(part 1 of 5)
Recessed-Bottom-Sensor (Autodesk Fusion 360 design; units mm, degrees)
parameter "FrameLength" = 640 comment "Fixed existing outer length"
parameter "FrameWidth" = 190 comment "Fixed existing outer width"
parameter "FrameHeight" = 110 comment "Fixed existing height"
parameter "PivotHeight" = 18 comment "Above frame center"
parameter "LeverTravel" = 100 comment "Stable endpoint to endpoint"
parameter "PrintClearance" = 0.3 comment "Prototype diametral running clearance"
base_mesh_feature "Base Mesh Feature"
ground "Pin1"
work_plane "WorkPlane1" AlongDistance -36 ExtraOffset 0
sketch "Flat load-bearing plate" plane through (-36, 0, 0) normal (1, 0, 0) x axis (0, 0, -1)
  line L1 (-33, -55) -> (-33, -75)
  line L2 (2, -55) -> (-33, -55)
  line L3 (2, 55) -> (2, -55)
  line L4 (-33, 55) -> (2, 55)
  line L5 (-33, 75) -> (-33, 55)
  line L6 (-57, 75) -> (-33, 75)
  line L7 (-57, 32) -> (-57, 75)
  line L8 (-86, 26) -> (-57, 32)
  line L9 (-86, -26) -> (-86, 26)
  line L10 (-57, -32) -> (-86, -26)
  line L11 (-57, -75) -> (-57, -32)
  line L12 (-33, -75) -> (-57, -75)
extrude "Extrude1" new body sketch "Flat load-bearing plate" along normal blind 12
work_plane "WorkPlane2" AlongDistance -37 ExtraOffset 0
sketch "Replaceable bushing seat" plane through (-37, 0, 0) normal (1, 0, 0) x axis (0, 0, -1)
  circle C1 centre (-65, 0) radius 10.15
extrude "Extrude2" cut sketch "Replaceable bushing seat" along normal blind 14
work_plane "WorkPlane3" AlongDistance -37 ExtraOffset 0
sketch "Follower pivot bolt" plane through (-37, 0, 0) normal (1, 0, 0) x axis (0, 0, -1)
  circle C1 centre (-12, -35) radius 2.7
extrude "Extrude3" cut sketch "Follower pivot bolt" along normal blind 14
work_plane "WorkPlane4" AlongDistance -76 ExtraOffset 0
sketch "M5 rail mounting bore" plane through (0, -76, 0) normal (0, 1, 0) x axis (1, 0, 0)
  circle C1 centre (-30, -45) radius 2.7
extrude "Extrude4" cut sketch "M5 rail mounting bore" along normal blind 22
work_plane "WorkPlane5" AlongDistance -55 ExtraOffset 0
sketch "Rail screw tool and washer access" plane through (0, -55, 0) normal (0, 1, 0) x axis (1, 0, 0)
  circle C1 centre (-30, -45) radius 5.3
extrude "Extrude5" cut sketch "Rail screw tool and washer access" along normal blind 12
work_plane "WorkPlane6" AlongDistance 54 ExtraOffset 0
sketch "M5 rail mounting bore (1)" plane through (0, 54, 0) normal (0, 1, 0) x axis (1, 0, 0)
  circle C1 centre (-30, -45) radius 2.7
extrude "Extrude6" cut sketch "M5 rail mounting bore (1)" along normal blind 22
work_plane "WorkPlane7" AlongDistance 43 ExtraOffset 0
sketch "Rail screw tool and washer access (1)" plane through (0, 43, 0) normal (0, 1, 0) x axis (1, 0, 0)
  circle C1 centre (-30, -45) radius 5.3
extrude "Extrude7" cut sketch "Rail screw tool and washer access (1)" along normal blind 12
work_plane "WorkPlane8" AlongDistance -37 ExtraOffset 0
sketch "Spring crossblock attachment" plane through (-37, 0, 0) normal (1, 0, 0) x axis (0, 0, -1)
  circle C1 centre (-44, -59) radius 1.7
extrude "Extrude8" cut sketch "Spring crossblock attachment" along normal blind 14
work_plane "WorkPlane9" AlongDistance -37 ExtraOffset 0
sketch "Spring crossblock attachment (1)" plane through (-37, 0, 0) normal (1, 0, 0) x axis (0, 0, -1)
  circle C1 centre (-44, -51) radius 1.7
extrude "Extrude9" cut sketch "Spring crossblock attachment (1)" along normal blind 14
work_plane "WorkPlane1" AlongDistance 24 ExtraOffset 0
sketch "Flat load-bearing plate" plane through (24, 0, 0) normal (1, 0, 0) x axis (0, 0, -1)
  line L1 (-33, -55) -> (-33, -75)
  line L2 (2, -55) -> (-33, -55)
  line L3 (2, 55) -> (2, -55)
  line L4 (-33, 55) -> (2, 55)
  line L5 (-33, 75) -> (-33, 55)
  line L6 (-57, 75) -> (-33, 75)
  line L7 (-57, 32) -> (-57, 75)
  line L8 (-86, 26) -> (-57, 32)
  line L9 (-86, -26) -> (-86, 26)
  line L10 (-57, -32) -> (-86, -26)
  line L11 (-57, -75) -> (-57, -32)
  line L12 (-33, -75) -> (-57, -75)
extrude "Extrude1" new body sketch "Flat load-bearing plate" along normal blind 12
work_plane "WorkPlane2" AlongDistance 23 ExtraOffset 0
sketch "Replaceable bushing seat" plane through (23, 0, 0) normal (1, 0, 0) x axis (0, 0, -1)
  circle C1 centre (-65, 0) radius 10.15
extrude "Extrude2" cut sketch "Replaceable bushing seat" along normal blind 14
work_plane "WorkPlane3" AlongDistance 23 ExtraOffset 0
sketch "Follower pivot bolt" plane through (23, 0, 0) normal (1, 0, 0) x axis (0, 0, -1)
  circle C1 centre (-12, -35) radius 2.7
extrude "Extrude3" cut sketch "Follower pivot bolt" along normal blind 14
work_plane "WorkPlane4" AlongDistance -76 ExtraOffset 0
sketch "M5 rail mounting bore" plane through (0, -76, 0) normal (0, 1, 0) x axis (1, 0, 0)
  circle C1 centre (30, -45) radius 2.7
extrude "Extrude4" cut sketch "M5 rail mounting bore" along normal blind 22
work_plane "WorkPlane5" AlongDistance -55 ExtraOffset 0
sketch "Rail screw tool and washer access" plane through (0, -55, 0) normal (0, 1, 0) x axis (1, 0, 0)
  circle C1 centre (30, -45) radius 5.3
extrude "Extrude5" cut sketch "Rail screw tool and washer access" along normal blind 12
work_plane "WorkPlane6" AlongDistance 54 ExtraOffset 0
sketch "M5 rail mounting bore (1)" plane through (0, 54, 0) normal (0, 1, 0) x axis (1, 0, 0)
  circle C1 centre (30, -45) radius 2.7
extrude "Extrude6" cut sketch "M5 rail mounting bore (1)" along normal blind 22
work_plane "WorkPlane7" AlongDistance 43 ExtraOffset 0
sketch "Rail screw tool and washer access (1)" plane through (0, 43, 0) normal (0, 1, 0) x axis (1, 0, 0)
  circle C1 centre (30, -45) radius 5.3
extrude "Extrude7" cut sketch "Rail screw tool and washer access (1)" along normal blind 12
work_plane "WorkPlane8" AlongDistance 23 ExtraOffset 0
sketch "Spring crossblock attachment" plane through (23, 0, 0) normal (1, 0, 0) x axis (0, 0, -1)
  circle C1 centre (-44, -59) radius 1.7
extrude "Extrude8" cut sketch "Spring crossblock attachment" along normal blind 14
work_plane "WorkPlane9" AlongDistance 23 ExtraOffset 0
sketch "Spring crossblock attachment (1)" plane through (23, 0, 0) normal (1, 0, 0) x axis (0, 0, -1)
  circle C1 centre (-44, -51) radius 1.7
extrude "Extrude9" cut sketch "Spring crossblock attachment (1)" along normal blind 14
work_plane "WorkPlane1" AlongDistance -36 ExtraOffset 0
sketch "Replaceable journal body" plane through (-36, 0, 0) normal (1, 0, 0) x axis (0, 0, -1)
  circle C1 centre (-65, 0) radius 10.05
extrude "Extrude1" new body sketch "Replaceable journal body" along normal blind 12 bodies "P03 Left flanged journal bush"
work_plane "WorkPlane2" AlongDistance -37.2 ExtraOffset 0
sketch "Axial thrust flange" plane through (-37.2, 0, 0) normal (1, 0, 0) x axis (0, 0, -1)
  circle C1 centre (-65, 0) radius 12.75
extrude "Extrude2" add sketch "Axial thrust flange" along normal blind 1.2
work_plane "WorkPlane3" AlongDistance -38 ExtraOffset 0
sketch "Running journal bore" plane through (-38, 0, 0) normal (1, 0, 0) x axis (0, 0, -1)
  circle C1 centre (-65, 0) radius 6.15
extrude "Extrude3" cut sketch "Running journal bore" along normal blind 15
work_plane "WorkPlane1" AlongDistance 24 ExtraOffset 0
sketch "Replaceable journal body" plane through (24, 0, 0) normal (1, 0, 0) x axis (0, 0, -1)
  circle C1 centre (-65, 0) radius 10.05
extrude "Extrude1" new body sketch "Replaceable journal body" along normal blind 12 bodies "P04 Right flanged journal bush"
work_plane "WorkPlane2" AlongDistance 36 ExtraOffset 0
sketch "Axial thrust flange" plane through (36, 0, 0) normal (1, 0, 0) x axis (0, 0, -1)
  circle C1 centre (-65, 0) radius 12.75
extrude "Extrude2" add sketch "Axial thrust flange" along normal blind 1.2
work_plane "WorkPlane3" AlongDistance 23 ExtraOffset 0
sketch "Running journal bore" plane through (23, 0, 0) normal (1, 0, 0) x axis (0, 0, -1)
  circle C1 centre (-65, 0) radius 6.15
extrude "Extrude3" cut sketch "Running journal bore" along normal blind 15
work_plane "WorkPlane1" AlongDistance -39.35 ExtraOffset 0
sketch "Axial cap" plane through (-39.35, 0, 0) normal (1, 0, 0) x axis (0, 0, -1)
  circle C1 centre (-65, 0) radius 10
extrude "Extrude1" new body sketch "Axial cap" along normal blind 2 bodies "P06 Shaft retaining cap"
work_plane "WorkPlane2" AlongDistance -39.5 ExtraOffset 0
sketch "M3 cap screw" plane through (-39.5, 0, 0) normal (1, 0, 0) x axis (0, 0, -1)
  circle C1 centre (-65, 0) radius 1.7
extrude "Extrude2" cut sketch "M3 cap screw" along normal blind 2.4
work_plane "WorkPlane1" AlongDistance -7 ExtraOffset 0
sketch "Main lever hub" plane through (-7, 0, 0) normal (1, 0, 0) x axis (0, 0, -1)
  circle C1 centre (-65, 0) radius 22
extrude "Extrude1" new body sketch "Main lever hub" along normal blind 14 bodies "P07 Integral lever rotor and cam carrier"
work_plane "WorkPlane2" AlongDistance -7 ExtraOffset 0
sketch "Continuous reinforced lever stem" plane through (-7, 0, 0) normal (1, 0, 0) x axis (0, 0, -1)
  line L1 (-60, 14) -> (-60, -14)
  line L2 (-95, 11) -> (-60, 14)
  line L3 (-150, 7) -> (-95, 11)
  line L4 (-195, 7) -> (-150, 7)
  line L5 (-195, -7) -> (-195, 7)
  line L6 (-150, -7) -> (-195, -7)
  line L7 (-95, -11) -> (-150, -7)
  line L8 (-60, -14) -> (-95, -11)
extrude "Extrude2" add sketch "Continuous reinforced lever stem" along normal blind 14
work_plane "WorkPlane3" AlongDistance -7 ExtraOffset 0
sketch "Integrated cam carrier fan" plane through (-7, 0, 0) normal (1, 0, 0) x axis (0, 0, -1)
  line L1 (-44.5, 35.507) -> (-65, 0)
  line L2 (-42.6698, 34.3855) -> (-44.5, 35.507)
  line L3 (-40.9008, 33.1697) -> (-42.6698, 34.3855)
  line L4 (-39.1979, 31.863) -> (-40.9008, 33.1697)
  line L5 (-37.5656, 30.4689) -> (-39.1979, 31.863)
  line L6 (-36.0086, 28.9914) -> (-37.5656, 30.4689)
  line L7 (-34.5311, 27.4344) -> (-36.0086, 28.9914)
  line L8 (-33.137, 25.8021) -> (-34.5311, 27.4344)
  line L9 (-31.8303, 24.0992) -> (-33.137, 25.8021)
  line L10 (-30.6145, 22.3302) -> (-31.8303, 24.0992)
  line L11 (-29.493, 20.5) -> (-30.6145, 22.3302)
  line L12 (-28.4687, 18.6136) -> (-29.493, 20.5)
  line L13 (-27.5446, 16.6762) -> (-28.4687, 18.6136)
  line L14 (-26.7232, 14.6931) -> (-27.5446, 16.6762)
  line L15 (-26.0067, 12.6697) -> (-26.7232, 14.6931)
  line L16 (-25.397, 10.6116) -> (-26.0067, 12.6697)
  line L17 (-24.8959, 8.5244) -> (-25.397, 10.6116)
  line L18 (-24.5048, 6.4138) -> (-24.8959, 8.5244)
  line L19 (-24.2246, 4.2857) -> (-24.5048, 6.4138)
  line L20 (-24.0562, 2.1458) -> (-24.2246, 4.2857)
  line L21 (-24, 0) -> (-24.0562, 2.1458)
  line L22 (-24.0562, -2.1458) -> (-24, 0)
  line L23 (-24.2246, -4.2857) -> (-24.0562, -2.1458)
  line L24 (-24.5048, -6.4138) -> (-24.2246, -4.2857)
  line L25 (-24.8959, -8.5244) -> (-24.5048, -6.4138)
  line L26 (-25.397, -10.6116) -> (-24.8959, -8.5244)
  line L27 (-26.0067, -12.6697) -> (-25.397, -10.6116)
  line L28 (-26.7232, -14.6931) -> (-26.0067, -12.6697)
  line L29 (-27.5446, -16.6762) -> (-26.7232, -14.6931)
  line L30 (-28.4687, -18.6136) -> (-27.5446, -16.6762)
  line L31 (-29.493, -20.5) -> (-28.4687, -18.6136)
  line L32 (-30.6145, -22.3302) -> (-29.493, -20.5)
  line L33 (-31.8303, -24.0992) -> (-30.6145, -22.3302)
  line L34 (-33.137, -25.8021) -> (-31.8303, -24.0992)
  line L35 (-34.5311, -27.4344) -> (-33.137, -25.8021)
  line L36 (-36.0086, -28.9914) -> (-34.5311, -27.4344)
  line L37 (-37.5656, -30.4689) -> (-36.0086, -28.9914)
  line L38 (-39.1979, -31.863) -> (-37.5656, -30.4689)
  line L39 (-40.9008, -33.1697) -> (-39.1979, -31.863)
  line L40 (-42.6698, -34.3855) -> (-40.9008, -33.1697)
  line L41 (-44.5, -35.507) -> (-42.6698, -34.3855)
  line L42 (-65, 0) -> (-44.5, -35.507)
extrude "Extrude3" add sketch "Integrated cam carrier fan" along normal blind 14
work_plane "WorkPlane4" AlongDistance -23.6 ExtraOffset 0
sketch "Integral axial locating hub" plane through (-23.6, 0, 0) normal (1, 0, 0) x axis (0, 0, -1)
  circle C1 centre (-65, 0) radius 10
work_plane "WorkPlane5" AlongDistance -24 ExtraOffset 0
sketch "D shaft socket" plane through (-24, 0, 0) normal (1, 0, 0) x axis (0, 0, -1)
  line L1 (-69.6247, 6.65) -> (-60.3753, 6.65)
  arc A1 centre (-65, 0) radius 8.1 clockwise from (-60.3753, 6.65) to (-69.6247, 6.65)
extrude "Extrude5" cut sketch "D shaft socket" along normal blind 48
work_plane "WorkPlane6" AlongDistance 0.3 ExtraOffset 0
sketch "Cam M3 insert pocket" plane through (0.3, 0, 0) normal (1, 0, 0) x axis (0, 0, -1)
  circle C1 centre (-39.5442, 25.4558) radius 2
extrude "Extrude6" cut sketch "Cam M3 insert pocket" along normal blind 6.8
work_plane "WorkPlane7" AlongDistance 0.3 ExtraOffset 0
sketch "Cam M3 insert pocket (1)" plane through (0.3, 0, 0) normal (1, 0, 0) x axis (0, 0, -1)
  circle C1 centre (-29, 0) radius 2
extrude "Extrude7" cut sketch "Cam M3 insert pocket (1)" along normal blind 6.8
work_plane "WorkPlane8" AlongDistance 0.3 ExtraOffset 0
sketch "Cam M3 insert pocket (2)" plane through (0.3, 0, 0) normal (1, 0, 0) x axis (0, 0, -1)
  circle C1 centre (-39.5442, -25.4558) radius 2
extrude "Extrude8" cut sketch "Cam M3 insert pocket (2)" along normal blind 6.8
work_plane "WorkPlane9" AlongDistance -8 ExtraOffset 0
sketch "Grip through bolt" plane through (-8, 0, 0) normal (1, 0, 0) x axis (0, 0, -1)
  circle C1 centre (-180, 0) radius 1.7
extrude "Extrude9" cut sketch "Grip through bolt" along normal blind 16
work_plane "WorkPlane10" AlongDistance -8 ExtraOffset 0
sketch "Grip through bolt (1)" plane through (-8, 0, 0) normal (1, 0, 0) x axis (0, 0, -1)
  circle C1 centre (-190, 0) radius 1.7
extrude "Extrude10" cut sketch "Grip through bolt (1)" along normal blind 16
work_plane "WorkPlane1" AlongDistance 7 ExtraOffset 0
sketch "Roller compensated replaceable cam" plane through (7, 0, 0) normal (1, 0, 0) x axis (0, 0, -1)
  line L1 (-39.4967, 42.2602) -> (-39.6212, 42.3096)
  line L2 (-39.3834, 42.211) -> (-39.4967, 42.2602)
  line L3 (-39.2796, 42.1617) -> (-39.3834, 42.211)
  line L4 (-39.1836, 42.1119) -> (-39.2796, 42.1617)
  line L5 (-39.0932, 42.0608) -> (-39.1836, 42.1119)
  line L6 (-39.0065, 42.0075) -> (-39.0932, 42.0608)
  line L7 (-38.9215, 41.9508) -> (-39.0065, 42.0075)
  line L8 (-38.8363, 41.8895) -> (-38.9215, 41.9508)
  line L9 (-38.7492, 41.8219) -> (-38.8363, 41.8895)
  line L10 (-38.6586, 41.7465) -> (-38.7492, 41.8219)
  line L11 (-38.5633, 41.6619) -> (-38.6586, 41.7465)
  line L12 (-38.4623, 41.5665) -> (-38.5633, 41.6619)
  line L13 (-38.3549, 41.459) -> (-38.4623, 41.5665)
  line L14 (-38.2404, 41.3384) -> (-38.3549, 41.459)
  line L15 (-38.1184, 41.204) -> (-38.2404, 41.3384)
  line L16 (-37.9886, 41.055) -> (-38.1184, 41.204)
  line L17 (-37.8508, 40.8913) -> (-37.9886, 41.055)
  line L18 (-37.7045, 40.7127) -> (-37.8508, 40.8913)
  line L19 (-37.5496, 40.5196) -> (-37.7045, 40.7127)
  line L20 (-37.3856, 40.3123) -> (-37.5496, 40.5196)
  line L21 (-37.2122, 40.0915) -> (-37.3856, 40.3123)
  line L22 (-37.0289, 39.858) -> (-37.2122, 40.0915)
  line L23 (-36.8353, 39.6128) -> (-37.0289, 39.858)
  line L24 (-36.6306, 39.3571) -> (-36.8353, 39.6128)
  line L25 (-36.4145, 39.0923) -> (-36.6306, 39.3571)
  line L26 (-36.1865, 38.82) -> (-36.4145, 39.0923)
  line L27 (-35.9461, 38.5417) -> (-36.1865, 38.82)
  line L28 (-35.6932, 38.2594) -> (-35.9461, 38.5417)
  line L29 (-35.4277, 37.9751) -> (-35.6932, 38.2594)
  line L30 (-35.15, 37.6908) -> (-35.4277, 37.9751)
  line L31 (-34.8607, 37.4087) -> (-35.15, 37.6908)
  line L32 (-34.5606, 37.1307) -> (-34.8607, 37.4087)
  line L33 (-34.2512, 36.859) -> (-34.5606, 37.1307)
  line L34 (-33.934, 36.5953) -> (-34.2512, 36.859)
  line L35 (-33.6109, 36.341) -> (-33.934, 36.5953)
  line L36 (-33.2841, 36.0975) -> (-33.6109, 36.341)
  line L37 (-32.9558, 35.8655) -> (-33.2841, 36.0975)
  line L38 (-32.6282, 35.6454) -> (-32.9558, 35.8655)
  line L39 (-32.3036, 35.4375) -> (-32.6282, 35.6454)
  line L40 (-31.984, 35.2415) -> (-32.3036, 35.4375)
  line L41 (-31.6712, 35.057) -> (-31.984, 35.2415)
  line L42 (-31.3671, 34.8833) -> (-31.6712, 35.057)
  line L43 (-31.073, 34.7197) -> (-31.3671, 34.8833)
  line L44 (-30.7902, 34.5655) -> (-31.073, 34.7197)
  line L45 (-30.52, 34.4197) -> (-30.7902, 34.5655)
  line L46 (-30.263, 34.2816) -> (-30.52, 34.4197)
  line L47 (-30.0201, 34.1506) -> (-30.263, 34.2816)
  line L48 (-29.7919, 34.0259) -> (-30.0201, 34.1506)
  line L49 (-29.5787, 33.9071) -> (-29.7919, 34.0259)
  line L50 (-29.3807, 33.7939) -> (-29.5787, 33.9071)
  line L51 (-29.1982, 33.6858) -> (-29.3807, 33.7939)
  line L52 (-29.0309, 33.5827) -> (-29.1982, 33.6858)
  line L53 (-28.8786, 33.4843) -> (-29.0309, 33.5827)
  line L54 (-28.7406, 33.3906) -> (-28.8786, 33.4843)
  line L55 (-28.6164, 33.3013) -> (-28.7406, 33.3906)
  line L56 (-28.5047, 33.2161) -> (-28.6164, 33.3013)
  line L57 (-28.4046, 33.1346) -> (-28.5047, 33.2161)
  line L58 (-28.3144, 33.0563) -> (-28.4046, 33.1346)
  line L59 (-28.2327, 32.9802) -> (-28.3144, 33.0563)
  line L60 (-28.1577, 32.9052) -> (-28.2327, 32.9802)
  line L61 (-28.0879, 32.8301) -> (-28.1577, 32.9052)
  line L62 (-28.0214, 32.7532) -> (-28.0879, 32.8301)
  line L63 (-27.9569, 32.6728) -> (-28.0214, 32.7532)
  line L64 (-27.893, 32.5869) -> (-27.9569, 32.6728)
  line L65 (-27.8285, 32.4936) -> (-27.893, 32.5869)
  line L66 (-27.7627, 32.3911) -> (-27.8285, 32.4936)
  line L67 (-27.6947, 32.2776) -> (-27.7627, 32.3911)
  line L68 (-27.6241, 32.1514) -> (-27.6947, 32.2776)
  line L69 (-27.5507, 32.0113) -> (-27.6241, 32.1514)
  line L70 (-27.4742, 31.8562) -> (-27.5507, 32.0113)
  line L71 (-27.3945, 31.6853) -> (-27.4742, 31.8562)
  line L72 (-27.3113, 31.4981) -> (-27.3945, 31.6853)
  line L73 (-27.2245, 31.2943) -> (-27.3113, 31.4981)
  line L74 (-27.1338, 31.074) -> (-27.2245, 31.2943)
  line L75 (-27.0388, 30.8373) -> (-27.1338, 31.074)
  line L76 (-26.939, 30.5847) -> (-27.0388, 30.8373)
  line L77 (-26.8337, 30.3166) -> (-26.939, 30.5847)
  line L78 (-26.7223, 30.034) -> (-26.8337, 30.3166)
  line L79 (-26.6038, 29.7375) -> (-26.7223, 30.034)
  line L80 (-26.4775, 29.4284) -> (-26.6038, 29.7375)
  line L81 (-26.3424, 29.1079) -> (-26.4775, 29.4284)
  line L82 (-26.1977, 28.7772) -> (-26.3424, 29.1079)
  line L83 (-26.0425, 28.4382) -> (-26.1977, 28.7772)
  line L84 (-25.8761, 28.0925) -> (-26.0425, 28.4382)
  line L85 (-25.6981, 27.7422) -> (-25.8761, 28.0925)
  line L86 (-25.5084, 27.3893) -> (-25.6981, 27.7422)
  line L87 (-25.3069, 27.0362) -> (-25.5084, 27.3893)
  line L88 (-25.0943, 26.6851) -> (-25.3069, 27.0362)
  line L89 (-24.8713, 26.3382) -> (-25.0943, 26.6851)
  line L90 (-24.6392, 25.9976) -> (-24.8713, 26.3382)
  line L91 (-24.3995, 25.6653) -> (-24.6392, 25.9976)
  line L92 (-24.1539, 25.3428) -> (-24.3995, 25.6653)
  line L93 (-23.9045, 25.0314) -> (-24.1539, 25.3428)
  line L94 (-23.6532, 24.7321) -> (-23.9045, 25.0314)
  line L95 (-23.4022, 24.4455) -> (-23.6532, 24.7321)
  line L96 (-23.1534, 24.1718) -> (-23.4022, 24.4455)
  line L97 (-22.9088, 23.9111) -> (-23.1534, 24.1718)
  line L98 (-22.6701, 23.6631) -> (-22.9088, 23.9111)
  line L99 (-22.4387, 23.4276) -> (-22.6701, 23.6631)
  line L100 (-22.2162, 23.204) -> (-22.4387, 23.4276)
  line L101 (-22.0036, 22.9918) -> (-22.2162, 23.204)
  line L102 (-21.8021, 22.7907) -> (-22.0036, 22.9918)
  line L103 (-21.6123, 22.6001) -> (-21.8021, 22.7907)
  line L104 (-21.435, 22.4197) -> (-21.6123, 22.6001)
  line L105 (-21.2706, 22.2491) -> (-21.435, 22.4197)
  line L106 (-21.1193, 22.088) -> (-21.2706, 22.2491)
  line L107 (-20.9813, 21.9362) -> (-21.1193, 22.088)
  line L108 (-20.8565, 21.7934) -> (-20.9813, 21.9362)
  line L109 (-20.7443, 21.6594) -> (-20.8565, 21.7934)
  line L110 (-20.6444, 21.5337) -> (-20.7443, 21.6594)
  line L111 (-20.556, 21.4159) -> (-20.6444, 21.5337)
  line L112 (-20.478, 21.3055) -> (-20.556, 21.4159)
  line L113 (-20.4094, 21.2014) -> (-20.478, 21.3055)
  line L114 (-20.349, 21.1027) -> (-20.4094, 21.2014)
  line L115 (-20.2954, 21.0079) -> (-20.349, 21.1027)
  line L116 (-20.2475, 20.9154) -> (-20.2954, 21.0079)
  line L117 (-20.2039, 20.8234) -> (-20.2475, 20.9154)
  line L118 (-20.1637, 20.7297) -> (-20.2039, 20.8234)
  line L119 (-20.126, 20.6321) -> (-20.1637, 20.7297)
  line L120 (-20.0901, 20.5286) -> (-20.126, 20.6321)
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extrude "Extrude1" new body sketch "Roller compensated replaceable cam" along normal blind 8 bodies "P08 Cam 7 gates - stable endpoints"
work_plane "WorkPlane2" AlongDistance 6.9 ExtraOffset 0
sketch "Cam screw clearance" plane through (6.9, 0, 0) normal (1, 0, 0) x axis (0, 0, -1)
  circle C1 centre (-39.5442, 25.4558) radius 1.7
extrude "Extrude2" cut sketch "Cam screw clearance" along normal blind 8.2
work_plane "WorkPlane3" AlongDistance 12 ExtraOffset 0
sketch "Cam head recess" plane through (12, 0, 0) normal (1, 0, 0) x axis (0, 0, -1)
  circle C1 centre (-39.5442, 25.4558) radius 3.1
extrude "Extrude3" cut sketch "Cam head recess" along normal blind 3.1
work_plane "WorkPlane4" AlongDistance 6.9 ExtraOffset 0
sketch "Cam screw clearance (1)" plane through (6.9, 0, 0) normal (1, 0, 0) x axis (0, 0, -1)
  circle C1 centre (-29, 0) radius 1.7
extrude "Extrude4" cut sketch "Cam screw clearance (1)" along normal blind 8.2
work_plane "WorkPlane5" AlongDistance 12 ExtraOffset 0
sketch "Cam head recess (1)" plane through (12, 0, 0) normal (1, 0, 0) x axis (0, 0, -1)
  circle C1 centre (-29, 0) radius 3.1
extrude "Extrude5" cut sketch "Cam head recess (1)" along normal blind 3.1
work_plane "WorkPlane6" AlongDistance 6.9 ExtraOffset 0
sketch "Cam screw clearance (2)" plane through (6.9, 0, 0) normal (1, 0, 0) x axis (0, 0, -1)
  circle C1 centre (-39.5442, -25.4558) radius 1.7
extrude "Extrude6" cut sketch "Cam screw clearance (2)" along normal blind 8.2
work_plane "WorkPlane7" AlongDistance 12 ExtraOffset 0
sketch "Cam head recess (2)" plane through (12, 0, 0) normal (1, 0, 0) x axis (0, 0, -1)
  circle C1 centre (-39.5442, -25.4558) radius 3.1
extrude "Extrude7" cut sketch "Cam head recess (2)" along normal blind 3.1
work_plane "WorkPlane1" AlongDistance 7 ExtraOffset 0
sketch "Roller compensated replaceable cam" plane through (7, 0, 0) normal (1, 0, 0) x axis (0, 0, -1)
  line L1 (-40.6423, 42.8316) -> (-40.8055, 42.9534)
  line L2 (-40.4783, 42.705) -> (-40.6423, 42.8316)
  line L3 (-40.3132, 42.5736) -> (-40.4783, 42.705)
  line L4 (-40.1469, 42.4372) -> (-40.3132, 42.5736)
  line L5 (-39.9791, 42.2958) -> (-40.1469, 42.4372)
  line L6 (-39.8097, 42.1493) -> (-39.9791, 42.2958)
  line L7 (-39.6386, 41.9977) -> (-39.8097, 42.1493)
  line L8 (-39.4656, 41.8411) -> (-39.6386, 41.9977)
  line L9 (-39.2906, 41.6794) -> (-39.4656, 41.8411)
  line L10 (-39.1134, 41.5128) -> (-39.2906, 41.6794)
  line L11 (-38.9338, 41.3413) -> (-39.1134, 41.5128)
  line L12 (-38.7519, 41.165) -> (-38.9338, 41.3413)
  line L13 (-38.5674, 40.9842) -> (-38.7519, 41.165)
  line L14 (-38.3803, 40.7991) -> (-38.5674, 40.9842)
  line L15 (-38.1904, 40.6097) -> (-38.3803, 40.7991)
  line L16 (-37.9976, 40.4164) -> (-38.1904, 40.6097)
  line L17 (-37.8019, 40.2195) -> (-37.9976, 40.4164)
  line L18 (-37.6031, 40.0191) -> (-37.8019, 40.2195)
  line L19 (-37.4011, 39.8157) -> (-37.6031, 40.0191)
  line L20 (-37.1958, 39.6094) -> (-37.4011, 39.8157)
  line L21 (-36.9872, 39.4008) -> (-37.1958, 39.6094)
  line L22 (-36.7753, 39.19) -> (-36.9872, 39.4008)
  line L23 (-36.5599, 38.9775) -> (-36.7753, 39.19)
  line L24 (-36.3411, 38.7636) -> (-36.5599, 38.9775)
  line L25 (-36.1189, 38.5488) -> (-36.3411, 38.7636)
  line L26 (-35.8933, 38.3333) -> (-36.1189, 38.5488)
  line L27 (-35.6644, 38.1177) -> (-35.8933, 38.3333)
  line L28 (-35.4322, 37.9021) -> (-35.6644, 38.1177)
  line L29 (-35.197, 37.6871) -> (-35.4322, 37.9021)
  line L30 (-34.9588, 37.473) -> (-35.197, 37.6871)
  line L31 (-34.7178, 37.2602) -> (-34.9588, 37.473)
  line L32 (-34.4743, 37.0489) -> (-34.7178, 37.2602)
  line L33 (-34.2286, 36.8395) -> (-34.4743, 37.0489)
  line L34 (-33.9808, 36.6322) -> (-34.2286, 36.8395)
  line L35 (-33.7314, 36.4274) -> (-33.9808, 36.6322)
  line L36 (-33.4806, 36.2252) -> (-33.7314, 36.4274)
  line L37 (-33.2289, 36.0258) -> (-33.4806, 36.2252)
  line L38 (-32.9765, 35.8294) -> (-33.2289, 36.0258)
  line L39 (-32.7239, 35.6361) -> (-32.9765, 35.8294)
  line L40 (-32.4714, 35.446) -> (-32.7239, 35.6361)
  line L41 (-32.2195, 35.259) -> (-32.4714, 35.446)
  line L42 (-31.9685, 35.0753) -> (-32.2195, 35.259)
  line L43 (-31.7188, 34.8948) -> (-31.9685, 35.0753)
  line L44 (-31.4708, 34.7175) -> (-31.7188, 34.8948)
  line L45 (-31.2249, 34.5432) -> (-31.4708, 34.7175)
  line L46 (-30.9813, 34.3719) -> (-31.2249, 34.5432)
  line L47 (-30.7405, 34.2034) -> (-30.9813, 34.3719)
  line L48 (-30.5027, 34.0377) -> (-30.7405, 34.2034)
  line L49 (-30.2682, 33.8746) -> (-30.5027, 34.0377)
  line L50 (-30.0373, 33.7139) -> (-30.2682, 33.8746)
  line L51 (-29.8103, 33.5555) -> (-30.0373, 33.7139)
  line L52 (-29.5875, 33.3992) -> (-29.8103, 33.5555)
  line L53 (-29.3689, 33.2448) -> (-29.5875, 33.3992)
  line L54 (-29.1548, 33.0923) -> (-29.3689, 33.2448)
  line L55 (-28.9455, 32.9414) -> (-29.1548, 33.0923)
  line L56 (-28.7409, 32.7921) -> (-28.9455, 32.9414)
  line L57 (-28.5413, 32.644) -> (-28.7409, 32.7921)
  line L58 (-28.3468, 32.4972) -> (-28.5413, 32.644)
  line L59 (-28.1574, 32.3515) -> (-28.3468, 32.4972)
  line L60 (-27.9732, 32.2068) -> (-28.1574, 32.3515)
  line L61 (-27.7942, 32.0628) -> (-27.9732, 32.2068)
  line L62 (-27.6204, 31.9196) -> (-27.7942, 32.0628)
  line L63 (-27.4518, 31.7769) -> (-27.6204, 31.9196)
  line L64 (-27.2884, 31.6347) -> (-27.4518, 31.7769)
  line L65 (-27.1301, 31.4927) -> (-27.2884, 31.6347)
  line L66 (-26.9767, 31.351) -> (-27.1301, 31.4927)
  line L67 (-26.8282, 31.2092) -> (-26.9767, 31.351)
  line L68 (-26.6843, 31.0673) -> (-26.8282, 31.2092)
  line L69 (-26.545, 30.925) -> (-26.6843, 31.0673)
  line L70 (-26.4101, 30.7822) -> (-26.545, 30.925)
  line L71 (-26.2793, 30.6387) -> (-26.4101, 30.7822)
  line L72 (-26.1524, 30.4942) -> (-26.2793, 30.6387)
  line L73 (-26.0293, 30.3485) -> (-26.1524, 30.4942)
  line L74 (-25.9096, 30.2013) -> (-26.0293, 30.3485)
  line L75 (-25.7932, 30.0524) -> (-25.9096, 30.2013)
  line L76 (-25.6797, 29.9015) -> (-25.7932, 30.0524)
  line L77 (-25.5691, 29.7482) -> (-25.6797, 29.9015)
  line L78 (-25.461, 29.5923) -> (-25.5691, 29.7482)
  line L79 (-25.3553, 29.4334) -> (-25.461, 29.5923)
  line L80 (-25.2517, 29.2713) -> (-25.3553, 29.4334)
  line L81 (-25.15, 29.1057) -> (-25.2517, 29.2713)
  line L82 (-25.0502, 28.9363) -> (-25.15, 29.1057)
  line L83 (-24.9519, 28.7628) -> (-25.0502, 28.9363)
  line L84 (-24.855, 28.5849) -> (-24.9519, 28.7628)
  line L85 (-24.7595, 28.4024) -> (-24.855, 28.5849)
  line L86 (-24.665, 28.2152) -> (-24.7595, 28.4024)
  line L87 (-24.5716, 28.023) -> (-24.665, 28.2152)
  line L88 (-24.4791, 27.8257) -> (-24.5716, 28.023)
  line L89 (-24.3873, 27.6231) -> (-24.4791, 27.8257)
  line L90 (-24.2961, 27.4152) -> (-24.3873, 27.6231)
  line L91 (-24.2054, 27.2019) -> (-24.2961, 27.4152)
  line L92 (-24.115, 26.9832) -> (-24.2054, 27.2019)
  line L93 (-24.0247, 26.7591) -> (-24.115, 26.9832)
  line L94 (-23.9346, 26.5296) -> (-24.0247, 26.7591)
  line L95 (-23.8442, 26.2947) -> (-23.9346, 26.5296)
  line L96 (-23.7536, 26.0546) -> (-23.8442, 26.2947)
  line L97 (-23.6625, 25.8094) -> (-23.7536, 26.0546)
  line L98 (-23.5707, 25.5592) -> (-23.6625, 25.8094)
  line L99 (-23.478, 25.3041) -> (-23.5707, 25.5592)
  line L100 (-23.3842, 25.0444) -> (-23.478, 25.3041)
  line L101 (-23.2891, 24.7802) -> (-23.3842, 25.0444)
  line L102 (-23.1926, 24.5118) -> (-23.2891, 24.7802)
  line L103 (-23.0943, 24.2394) -> (-23.1926, 24.5118)
  line L104 (-22.9942, 23.9633) -> (-23.0943, 24.2394)
  line L105 (-22.8919, 23.6838) -> (-22.9942, 23.9633)
  line L106 (-22.7873, 23.4012) -> (-22.8919, 23.6838)
  line L107 (-22.6803, 23.1157) -> (-22.7873, 23.4012)
  line L108 (-22.5706, 22.8278) -> (-22.6803, 23.1157)
  line L109 (-22.4581, 22.5379) -> (-22.5706, 22.8278)
  line L110 (-22.3428, 22.2461) -> (-22.4581, 22.5379)
  line L111 (-22.2245, 21.953) -> (-22.3428, 22.2461)
  line L112 (-22.1031, 21.659) -> (-22.2245, 21.953)
  line L113 (-21.9788, 21.3644) -> (-22.1031, 21.659)
  line L114 (-21.8513, 21.0696) -> (-21.9788, 21.3644)
  line L115 (-21.7209, 20.7751) -> (-21.8513, 21.0696)
  line L116 (-21.5876, 20.4811) -> (-21.7209, 20.7751)
  line L117 (-21.4516, 20.1882) -> (-21.5876, 20.4811)
  line L118 (-21.3129, 19.8966) -> (-21.4516, 20.1882)
  line L119 (-21.1718, 19.6067) -> (-21.3129, 19.8966)
  line L120 (-21.0286, 19.3189) -> (-21.1718, 19.6067)
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extrude "Extrude1" new body sketch "Roller compensated replaceable cam" along normal blind 8 bodies "P08 Cam 5 gates - stable endpoints"
work_plane "WorkPlane2" AlongDistance 6.9 ExtraOffset 0
sketch "Cam screw clearance" plane through (6.9, 0, 0) normal (1, 0, 0) x axis (0, 0, -1)
  circle C1 centre (-39.5442, 25.4558) radius 1.7
extrude "Extrude2" cut sketch "Cam screw clearance" along normal blind 8.2
work_plane "WorkPlane3" AlongDistance 12 ExtraOffset 0
sketch "Cam head recess" plane through (12, 0, 0) normal (1, 0, 0) x axis (0, 0, -1)
  circle C1 centre (-39.5442, 25.4558) radius 3.1
extrude "Extrude3" cut sketch "Cam head recess" along normal blind 3.1
work_plane "WorkPlane4" AlongDistance 6.9 ExtraOffset 0
sketch "Cam screw clearance (1)" plane through (6.9, 0, 0) normal (1, 0, 0) x axis (0, 0, -1)
  circle C1 centre (-29, 0) radius 1.7
extrude "Extrude4" cut sketch "Cam screw clearance (1)" along normal blind 8.2
work_plane "WorkPlane5" AlongDistance 12 ExtraOffset 0
sketch "Cam head recess (1)" plane through (12, 0, 0) normal (1, 0, 0) x axis (0, 0, -1)
  circle C1 centre (-29, 0) radius 3.1
extrude "Extrude5" cut sketch "Cam head recess (1)" along normal blind 3.1
work_plane "WorkPlane6" AlongDistance 6.9 ExtraOffset 0
sketch "Cam screw clearance (2)" plane through (6.9, 0, 0) normal (1, 0, 0) x axis (0, 0, -1)
  circle C1 centre (-39.5442, -25.4558) radius 1.7
extrude "Extrude6" cut sketch "Cam screw clearance (2)" along normal blind 8.2
work_plane "WorkPlane7" AlongDistance 12 ExtraOffset 0
sketch "Cam head recess (2)" plane through (12, 0, 0) normal (1, 0, 0) x axis (0, 0, -1)
  circle C1 centre (-39.5442, -25.4558) radius 3.1
extrude "Extrude7" cut sketch "Cam head recess (2)" along normal blind 3.1
work_plane "WorkPlane1" AlongDistance 7 ExtraOffset 0
sketch "Roller compensated replaceable cam" plane through (7, 0, 0) normal (1, 0, 0) x axis (0, 0, -1)
  line L1 (-40.92, 42.0772) -> (-41.1325, 42.2273)
  line L2 (-40.7077, 41.9259) -> (-40.92, 42.0772)
  line L3 (-40.4956, 41.7734) -> (-40.7077, 41.9259)
  line L4 (-40.2838, 41.6199) -> (-40.4956, 41.7734)
  line L5 (-40.0721, 41.4654) -> (-40.2838, 41.6199)
  line L6 (-39.8606, 41.3098) -> (-40.0721, 41.4654)
  line L7 (-39.6492, 41.1532) -> (-39.8606, 41.3098)
  line L8 (-39.4381, 40.9957) -> (-39.6492, 41.1532)
  line L9 (-39.2271, 40.8372) -> (-39.4381, 40.9957)
  line L10 (-39.0163, 40.6779) -> (-39.2271, 40.8372)
  line L11 (-38.8057, 40.5176) -> (-39.0163, 40.6779)
  line L12 (-38.5952, 40.3566) -> (-38.8057, 40.5176)
  line L13 (-38.3849, 40.1947) -> (-38.5952, 40.3566)
  line L14 (-38.1747, 40.032) -> (-38.3849, 40.1947)
  line L15 (-37.9647, 39.8686) -> (-38.1747, 40.032)
  line L16 (-37.7549, 39.7045) -> (-37.9647, 39.8686)
  line L17 (-37.5452, 39.5397) -> (-37.7549, 39.7045)
  line L18 (-37.3357, 39.3742) -> (-37.5452, 39.5397)
  line L19 (-37.1263, 39.2081) -> (-37.3357, 39.3742)
  line L20 (-36.9171, 39.0413) -> (-37.1263, 39.2081)
  line L21 (-36.7081, 38.874) -> (-36.9171, 39.0413)
  line L22 (-36.4992, 38.7061) -> (-36.7081, 38.874)
  line L23 (-36.2905, 38.5376) -> (-36.4992, 38.7061)
  line L24 (-36.082, 38.3687) -> (-36.2905, 38.5376)
  line L25 (-35.8737, 38.1992) -> (-36.082, 38.3687)
  line L26 (-35.6656, 38.0292) -> (-35.8737, 38.1992)
  line L27 (-35.4577, 37.8588) -> (-35.6656, 38.0292)
  line L28 (-35.25, 37.688) -> (-35.4577, 37.8588)
  line L29 (-35.0425, 37.5167) -> (-35.25, 37.688)
  line L30 (-34.8352, 37.3451) -> (-35.0425, 37.5167)
  line L31 (-34.6282, 37.173) -> (-34.8352, 37.3451)
  line L32 (-34.4215, 37.0006) -> (-34.6282, 37.173)
  line L33 (-34.215, 36.8278) -> (-34.4215, 37.0006)
  line L34 (-34.0088, 36.6547) -> (-34.215, 36.8278)
  line L35 (-33.8028, 36.4812) -> (-34.0088, 36.6547)
  line L36 (-33.5972, 36.3074) -> (-33.8028, 36.4812)
  line L37 (-33.392, 36.1333) -> (-33.5972, 36.3074)
  line L38 (-33.187, 35.9589) -> (-33.392, 36.1333)
  line L39 (-32.9825, 35.7842) -> (-33.187, 35.9589)
  line L40 (-32.7783, 35.6093) -> (-32.9825, 35.7842)
  line L41 (-32.5745, 35.434) -> (-32.7783, 35.6093)
  line L42 (-32.3711, 35.2584) -> (-32.5745, 35.434)
  line L43 (-32.1682, 35.0826) -> (-32.3711, 35.2584)
  line L44 (-31.9657, 34.9065) -> (-32.1682, 35.0826)
  line L45 (-31.7637, 34.7302) -> (-31.9657, 34.9065)
  line L46 (-31.5623, 34.5535) -> (-31.7637, 34.7302)
  line L47 (-31.3613, 34.3766) -> (-31.5623, 34.5535)
  line L48 (-31.1609, 34.1994) -> (-31.3613, 34.3766)
  line L49 (-30.9611, 34.0219) -> (-31.1609, 34.1994)
  line L50 (-30.7619, 33.8442) -> (-30.9611, 34.0219)
  line L51 (-30.5634, 33.6662) -> (-30.7619, 33.8442)
  line L52 (-30.3654, 33.4878) -> (-30.5634, 33.6662)
  line L53 (-30.1682, 33.3092) -> (-30.3654, 33.4878)
  line L54 (-29.9717, 33.1303) -> (-30.1682, 33.3092)
  line L55 (-29.7759, 32.9511) -> (-29.9717, 33.1303)
  line L56 (-29.5809, 32.7715) -> (-29.7759, 32.9511)
  line L57 (-29.3866, 32.5916) -> (-29.5809, 32.7715)
  line L58 (-29.1932, 32.4114) -> (-29.3866, 32.5916)
  line L59 (-29.0007, 32.2308) -> (-29.1932, 32.4114)
  line L60 (-28.809, 32.0499) -> (-29.0007, 32.2308)
  line L61 (-28.6182, 31.8686) -> (-28.809, 32.0499)
  line L62 (-28.4284, 31.6869) -> (-28.6182, 31.8686)
  line L63 (-28.2395, 31.5048) -> (-28.4284, 31.6869)
  line L64 (-28.0516, 31.3224) -> (-28.2395, 31.5048)
  line L65 (-27.8647, 31.1395) -> (-28.0516, 31.3224)
  line L66 (-27.6789, 30.9562) -> (-27.8647, 31.1395)
  line L67 (-27.4942, 30.7724) -> (-27.6789, 30.9562)
  line L68 (-27.3106, 30.5882) -> (-27.4942, 30.7724)
  line L69 (-27.1281, 30.4035) -> (-27.3106, 30.5882)
  line L70 (-26.9468, 30.2184) -> (-27.1281, 30.4035)
  line L71 (-26.7667, 30.0327) -> (-26.9468, 30.2184)
  line L72 (-26.5878, 29.8465) -> (-26.7667, 30.0327)
  line L73 (-26.4102, 29.6599) -> (-26.5878, 29.8465)
  line L74 (-26.2338, 29.4727) -> (-26.4102, 29.6599)
  line L75 (-26.0588, 29.2849) -> (-26.2338, 29.4727)
  line L76 (-25.8851, 29.0966) -> (-26.0588, 29.2849)
  line L77 (-25.7127, 28.9078) -> (-25.8851, 29.0966)
  line L78 (-25.5418, 28.7183) -> (-25.7127, 28.9078)
  line L79 (-25.3723, 28.5283) -> (-25.5418, 28.7183)
  line L80 (-25.2042, 28.3376) -> (-25.3723, 28.5283)
  line L81 (-25.0376, 28.1464) -> (-25.2042, 28.3376)
  line L82 (-24.8725, 27.9545) -> (-25.0376, 28.1464)
  line L83 (-24.7089, 27.762) -> (-24.8725, 27.9545)
  line L84 (-24.5469, 27.5688) -> (-24.7089, 27.762)
  line L85 (-24.3864, 27.375) -> (-24.5469, 27.5688)
  line L86 (-24.2275, 27.1805) -> (-24.3864, 27.375)
  line L87 (-24.0703, 26.9854) -> (-24.2275, 27.1805)
  line L88 (-23.9146, 26.7895) -> (-24.0703, 26.9854)
  line L89 (-23.7607, 26.593) -> (-23.9146, 26.7895)
  line L90 (-23.6084, 26.3958) -> (-23.7607, 26.593)
  line L91 (-23.4578, 26.1978) -> (-23.6084, 26.3958)
  line L92 (-23.3089, 25.9992) -> (-23.4578, 26.1978)
  line L93 (-23.1618, 25.7998) -> (-23.3089, 25.9992)
  line L94 (-23.0164, 25.5997) -> (-23.1618, 25.7998)
  line L95 (-22.8728, 25.3988) -> (-23.0164, 25.5997)
  line L96 (-22.7309, 25.1972) -> (-22.8728, 25.3988)
  line L97 (-22.5909, 24.9949) -> (-22.7309, 25.1972)
  line L98 (-22.4527, 24.7917) -> (-22.5909, 24.9949)
  line L99 (-22.3163, 24.5879) -> (-22.4527, 24.7917)
  line L100 (-22.1817, 24.3832) -> (-22.3163, 24.5879)
  line L101 (-22.049, 24.1778) -> (-22.1817, 24.3832)
  line L102 (-21.9182, 23.9716) -> (-22.049, 24.1778)
  line L103 (-21.7892, 23.7646) -> (-21.9182, 23.9716)
  line L104 (-21.6622, 23.5568) -> (-21.7892, 23.7646)
  line L105 (-21.537, 23.3482) -> (-21.6622, 23.5568)
  line L106 (-21.4137, 23.1388) -> (-21.537, 23.3482)
  line L107 (-21.2923, 22.9286) -> (-21.4137, 23.1388)
  line L108 (-21.1728, 22.7176) -> (-21.2923, 22.9286)
  line L109 (-21.0553, 22.5058) -> (-21.1728, 22.7176)
  line L110 (-20.9397, 22.2931) -> (-21.0553, 22.5058)
  line L111 (-20.8259, 22.0796) -> (-20.9397, 22.2931)
  line L112 (-20.7142, 21.8653) -> (-20.8259, 22.0796)
  line L113 (-20.6043, 21.6502) -> (-20.7142, 21.8653)
  line L114 (-20.4964, 21.4342) -> (-20.6043, 21.6502)
  line L115 (-20.3904, 21.2174) -> (-20.4964, 21.4342)
  line L116 (-20.2863, 20.9997) -> (-20.3904, 21.2174)
  line L117 (-20.1842, 20.7812) -> (-20.2863, 20.9997)
  line L118 (-20.0839, 20.5618) -> (-20.1842, 20.7812)
  line L119 (-19.9856, 20.3416) -> (-20.0839, 20.5618)
  line L120 (-19.8892, 20.1205) -> (-19.9856, 20.3416)
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extrude "Extrude1" new body sketch "Roller compensated replaceable cam" along normal blind 8 bodies "P08 Cam 3 gates - stable endpoints"
work_plane "WorkPlane2" AlongDistance 6.9 ExtraOffset 0
sketch "Cam screw clearance" plane through (6.9, 0, 0) normal (1, 0, 0) x axis (0, 0, -1)
  circle C1 centre (-39.5442, 25.4558) radius 1.7
extrude "Extrude2" cut sketch "Cam screw clearance" along normal blind 8.2
work_plane "WorkPlane3" AlongDistance 12 ExtraOffset 0
sketch "Cam head recess" plane through (12, 0, 0) normal (1, 0, 0) x axis (0, 0, -1)
  circle C1 centre (-39.5442, 25.4558) radius 3.1
extrude "Extrude3" cut sketch "Cam head recess" along normal blind 3.1
work_plane "WorkPlane4" AlongDistance 6.9 ExtraOffset 0
sketch "Cam screw clearance (1)" plane through (6.9, 0, 0) normal (1, 0, 0) x axis (0, 0, -1)
  circle C1 centre (-29, 0) radius 1.7
extrude "Extrude4" cut sketch "Cam screw clearance (1)" along normal blind 8.2
work_plane "WorkPlane5" AlongDistance 12 ExtraOffset 0
sketch "Cam head recess (1)" plane through (12, 0, 0) normal (1, 0, 0) x axis (0, 0, -1)
  circle C1 centre (-29, 0) radius 3.1
extrude "Extrude5" cut sketch "Cam head recess (1)" along normal blind 3.1
work_plane "WorkPlane6" AlongDistance 6.9 ExtraOffset 0
sketch "Cam screw clearance (2)" plane through (6.9, 0, 0) normal (1, 0, 0) x axis (0, 0, -1)
  circle C1 centre (-39.5442, -25.4558) radius 1.7
extrude "Extrude6" cut sketch "Cam screw clearance (2)" along normal blind 8.2
work_plane "WorkPlane7" AlongDistance 12 ExtraOffset 0
sketch "Cam head recess (2)" plane through (12, 0, 0) normal (1, 0, 0) x axis (0, 0, -1)
  circle C1 centre (-39.5442, -25.4558) radius 3.1
extrude "Extrude7" cut sketch "Cam head recess (2)" along normal blind 3.1
work_plane "WorkPlane1" AlongDistance 0 ExtraOffset 0
sketch "Palm grip smooth contour" plane through (0, 0, 0) normal (1, 0, 0) x axis (0, 0, -1)
  curve K1 (-225, 0) -> (-165, 12)
  line L1 (-225, 0) -> (-165, 0)
  line L2 (-165, 12) -> (-165, 0)
revolve "Revolve1" sketch "Palm grip smooth contour" AlongAngle 360 bodies "P09 Grip insert half"
work_plane "WorkPlane2" AlongDistance 0 ExtraOffset 0
sketch "Split on print bed face" plane through (0, 0, 0) normal (1, 0, 0) x axis (0, 0, -1)
  line L1 (-160, 30) -> (-160, -30)
  line L2 (-230, 30) -> (-160, 30)
  line L3 (-230, -30) -> (-230, 30)
  line L4 (-160, -30) -> (-230, -30)
extrude "Extrude1" cut sketch "Split on print bed face" along normal blind 30
work_plane "WorkPlane3" AlongDistance -7.2 ExtraOffset 0
sketch "Keyed stem socket" plane through (-7.2, 0, 0) normal (1, 0, 0) x axis (0, 0, -1)
  line L1 (-164, 7.2) -> (-164, -7.2)
  line L2 (-196, 7.2) -> (-164, 7.2)
  line L3 (-196, -7.2) -> (-196, 7.2)
  line L4 (-164, -7.2) -> (-196, -7.2)
extrude "Extrude2" cut sketch "Keyed stem socket" along normal blind 14.4
work_plane "WorkPlane4" AlongDistance -13.9 ExtraOffset 0
sketch "M3 grip heat set" plane through (-13.9, 0, 0) normal (1, 0, 0) x axis (0, 0, -1)
  circle C1 centre (-180, 0) radius 2
extrude "Extrude3" cut sketch "M3 grip heat set" along normal blind 6.8
work_plane "WorkPlane5" AlongDistance -13.9 ExtraOffset 0
sketch "M3 grip heat set (1)" plane through (-13.9, 0, 0) normal (1, 0, 0) x axis (0, 0, -1)
  circle C1 centre (-190, 0) radius 2
extrude "Extrude4" cut sketch "M3 grip heat set (1)" along normal blind 6.8
work_plane "WorkPlane1" AlongDistance 0 ExtraOffset 0
sketch "Palm grip smooth contour" plane through (0, 0, 0) normal (1, 0, 0) x axis (0, 0, -1)
  curve K1 (-225, 0) -> (-165, 12)
  line L1 (-225, 0) -> (-165, 0)
  line L2 (-165, 12) -> (-165, 0)
revolve "Revolve1" sketch "Palm grip smooth contour" AlongAngle 360 bodies "P10 Grip screw half"
work_plane "WorkPlane2" AlongDistance -30 ExtraOffset 0
sketch "Split on print bed face" plane through (-30, 0, 0) normal (1, 0, 0) x axis (0, 0, -1)
  line L1 (-160, 30) -> (-160, -30)
  line L2 (-230, 30) -> (-160, 30)
  line L3 (-230, -30) -> (-230, 30)
  line L4 (-160, -30) -> (-230, -30)
extrude "Extrude1" cut sketch "Split on print bed face" along normal blind 30
work_plane "WorkPlane3" AlongDistance -7.2 ExtraOffset 0
sketch "Keyed stem socket" plane through (-7.2, 0, 0) normal (1, 0, 0) x axis (0, 0, -1)
  line L1 (-164, 7.2) -> (-164, -7.2)
  line L2 (-196, 7.2) -> (-164, 7.2)
  line L3 (-196, -7.2) -> (-196, 7.2)
  line L4 (-164, -7.2) -> (-196, -7.2)
extrude "Extrude2" cut sketch "Keyed stem socket" along normal blind 14.4
work_plane "WorkPlane4" AlongDistance -0.1 ExtraOffset 0
sketch "Grip screw bore" plane through (-0.1, 0, 0) normal (1, 0, 0) x axis (0, 0, -1)
  circle C1 centre (-180, 0) radius 1.7
extrude "Extrude3" cut sketch "Grip screw bore" along normal blind 26
work_plane "WorkPlane5" AlongDistance 12.5 ExtraOffset 0
sketch "Recessed grip screw head" plane through (12.5, 0, 0) normal (1, 0, 0) x axis (0, 0, -1)
  circle C1 centre (-180, 0) radius 3.1
extrude "Extrude4" cut sketch "Recessed grip screw head" along normal blind 14
work_plane "WorkPlane6" AlongDistance -0.1 ExtraOffset 0
sketch "Grip screw bore (1)" plane through (-0.1, 0, 0) normal (1, 0, 0) x axis (0, 0, -1)
  circle C1 centre (-190, 0) radius 1.7
extrude "Extrude5" cut sketch "Grip screw bore (1)" along normal blind 26
work_plane "WorkPlane7" AlongDistance 12.5 ExtraOffset 0
sketch "Recessed grip screw head (1)" plane through (12.5, 0, 0) normal (1, 0, 0) x axis (0, 0, -1)
  circle C1 centre (-190, 0) radius 3.1
extrude "Extrude6" cut sketch "Recessed grip screw head (1)" along normal blind 14
work_plane "WorkPlane1" AlongDistance 4 ExtraOffset 0
sketch "First strong flat cheek" plane through (4, 0, 0) normal (1, 0, 0) x axis (0, 0, -1)
  line L1 (-6, -5) -> (-6, -61)
  line L2 (-7, 0) -> (-6, -5)
  line L3 (-17, 0) -> (-7, 0)
  line L4 (-18, -5) -> (-17, 0)
  line L5 (-18, -61) -> (-18, -5)
  line L6 (-6, -61) -> (-18, -61)
extrude "Extrude1" new body sketch "First strong flat cheek" along normal blind 3 bodies "P11 Forked roller follower"
work_plane "WorkPlane2" AlongDistance 4 ExtraOffset 0
sketch "Spring tail bridge" plane through (4, 0, 0) normal (1, 0, 0) x axis (0, 0, -1)
  line L1 (-6, -49) -> (-6, -61)
  line L2 (-18, -49) -> (-6, -49)
  line L3 (-18, -61) -> (-18, -49)
  line L4 (-6, -61) -> (-18, -61)
extrude "Extrude2" add sketch "Spring tail bridge" along normal blind 16
work_plane "WorkPlane3" AlongDistance 17 ExtraOffset 0
sketch "Second supporting cheek" plane through (17, 0, 0) normal (1, 0, 0) x axis (0, 0, -1)
  line L1 (-6, -5) -> (-6, -61)
  line L2 (-7, 0) -> (-6, -5)
  line L3 (-17, 0) -> (-7, 0)
  line L4 (-18, -5) -> (-17, 0)
  line L5 (-18, -61) -> (-18, -5)
  line L6 (-6, -61) -> (-18, -61)
extrude "Extrude3" add sketch "Second supporting cheek" along normal blind 3
work_plane "WorkPlane4" AlongDistance 4 ExtraOffset 0
sketch "Rounded roller cheek" plane through (4, 0, 0) normal (1, 0, 0) x axis (0, 0, -1)
  circle C1 centre (-12, 0) radius 6
extrude "Extrude4" add sketch "Rounded roller cheek" along normal blind 3
work_plane "WorkPlane5" AlongDistance 17 ExtraOffset 0
sketch "Rounded roller cheek (1)" plane through (17, 0, 0) normal (1, 0, 0) x axis (0, 0, -1)
  circle C1 centre (-12, 0) radius 6
extrude "Extrude5" add sketch "Rounded roller cheek (1)" along normal blind 3
work_plane "WorkPlane6" AlongDistance 3.9 ExtraOffset 0
sketch "Smooth pivot sleeve bore" plane through (3.9, 0, 0) normal (1, 0, 0) x axis (0, 0, -1)
  circle C1 centre (-12, -35) radius 4.15
extrude "Extrude6" cut sketch "Smooth pivot sleeve bore" along normal blind 16.2
work_plane "WorkPlane7" AlongDistance 3.9 ExtraOffset 0
sketch "Roller axle holes" plane through (3.9, 0, 0) normal (1, 0, 0) x axis (0, 0, -1)
  circle C1 centre (-12, 0) radius 1.7
extrude "Extrude7" cut sketch "Roller axle holes" along normal blind 16.2
work_plane "WorkPlane8" AlongDistance 3.9 ExtraOffset 0
sketch "Roller M3 nut recess" plane through (3.9, 0, 0) normal (1, 0, 0) x axis (0, 0, -1)
  line L1 (-14.9, 1.6743) -> (-12, 3.3486)
  line L2 (-14.9, -1.6743) -> (-14.9, 1.6743)
  line L3 (-12, -3.3486) -> (-14.9, -1.6743)
  line L4 (-9.1, -1.6743) -> (-12, -3.3486)
  line L5 (-9.1, 1.6743) -> (-9.1, -1.6743)
  line L6 (-12, 3.3486) -> (-9.1, 1.6743)
extrude "Extrude8" cut sketch "Roller M3 nut recess" along normal blind 1.6
work_plane "WorkPlane9" AlongDistance 18 ExtraOffset 0
sketch "Spring tail locating pilot" plane through (0, 0, 18) normal (0, 0, 1) x axis (1, 0, 0)
  circle C1 centre (12, -55) radius 1.8
extrude "Extrude9" add sketch "Spring tail locating pilot" along normal blind 2
work_plane "WorkPlane1" AlongDistance -24 ExtraOffset 0
sketch "Captured spring reaction block" plane through (-24, 0, 0) normal (1, 0, 0) x axis (0, 0, -1)
  line L1 (-38, -44) -> (-38, -66)
  line L2 (-52, -44) -> (-38, -44)
  line L3 (-52, -66) -> (-52, -44)
  line L4 (-38, -66) -> (-52, -66)
extrude "Extrude1" new body sketch "Captured spring reaction block" along normal blind 48
work_plane "WorkPlane2" AlongDistance -24.1 ExtraOffset 0
sketch "Left M3 insert with screw tip relief" plane through (-24.1, 0, 0) normal (1, 0, 0) x axis (0, 0, -1)
  circle C1 centre (-44, -59) radius 2
extrude "Extrude2" cut sketch "Left M3 insert with screw tip relief" along normal blind 8.8
work_plane "WorkPlane3" AlongDistance 15.3 ExtraOffset 0
sketch "Right M3 insert with screw tip relief" plane through (15.3, 0, 0) normal (1, 0, 0) x axis (0, 0, -1)
  circle C1 centre (-44, -59) radius 2
extrude "Extrude3" cut sketch "Right M3 insert with screw tip relief" along normal blind 8.8
work_plane "WorkPlane4" AlongDistance -24.1 ExtraOffset 0
sketch "Left M3 insert with screw tip relief (1)" plane through (-24.1, 0, 0) normal (1, 0, 0) x axis (0, 0, -1)
  circle C1 centre (-44, -51) radius 2
extrude "Extrude4" cut sketch "Left M3 insert with screw tip relief (1)" along normal blind 8.8
work_plane "WorkPlane5" AlongDistance 15.3 ExtraOffset 0
sketch "Right M3 insert with screw tip relief (1)" plane through (15.3, 0, 0) normal (1, 0, 0) x axis (0, 0, -1)
  circle C1 centre (-44, -51) radius 2
extrude "Extrude5" cut sketch "Right M3 insert with screw tip relief (1)" along normal blind 8.8
work_plane "WorkPlane6" AlongDistance 37.9 ExtraOffset 0
sketch "M4 preload adjuster" plane through (0, 0, 37.9) normal (0, 0, 1) x axis (1, 0, 0)
  circle C1 centre (12, -55) radius 2.2
extrude "Extrude6" cut sketch "M4 preload adjuster" along normal blind 14.2
work_plane "WorkPlane7" AlongDistance 37.9 ExtraOffset 0
sketch "Spring-side loaded retained M4 nut" plane through (0, 0, 37.9) normal (0, 0, 1) x axis (1, 0, 0)
  line L1 (14.1362, -51.3) -> (16.2724, -55)
  line L2 (9.8638, -51.3) -> (14.1362, -51.3)
  line L3 (7.7276, -55) -> (9.8638, -51.3)
  line L4 (9.8638, -58.7) -> (7.7276, -55)
  line L5 (14.1362, -58.7) -> (9.8638, -58.7)
  line L6 (16.2724, -55) -> (14.1362, -58.7)
extrude "Extrude7" cut sketch "Spring-side loaded retained M4 nut" along normal blind 3.5
work_plane "WorkPlane8" AlongDistance 37.9 ExtraOffset 0
sketch "Spring cup guide bolts" plane through (0, 0, 37.9) normal (0, 0, 1) x axis (1, 0, 0)
  circle C1 centre (5, -55) radius 1.7
extrude "Extrude8" cut sketch "Spring cup guide bolts" along normal blind 14.2
work_plane "WorkPlane9" AlongDistance 37.9 ExtraOffset 0
sketch "Spring cup guide bolts (1)" plane through (0, 0, 37.9) normal (0, 0, 1) x axis (1, 0, 0)
  circle C1 centre (19, -55) radius 1.7
extrude "Extrude9" cut sketch "Spring cup guide bolts (1)" along normal blind 14.2
work_plane "WorkPlane11" AlongDistance -18 ExtraOffset 0
sketch "Dedicated thick stop lug" plane through (-18, 0, 0) normal (1, 0, 0) x axis (0, 0, -1)
  line L1 (-72, 5) -> (-72, -5)
  line L2 (-95, 5) -> (-72, 5)
  line L3 (-95, -5) -> (-95, 5)
  line L4 (-72, -5) -> (-95, -5)
extrude "Extrude11" add sketch "Dedicated thick stop lug" along normal blind 11.5
work_plane "WorkPlane12" AlongDistance -18 ExtraOffset 0
sketch "Rounded stop contact" plane through (-18, 0, 0) normal (1, 0, 0) x axis (0, 0, -1)
  circle C1 centre (-95, 0) radius 5
extrude "Extrude12" add sketch "Rounded stop contact" along normal blind 11.5
work_plane "WorkPlane10" AlongDistance -36 ExtraOffset 0
sketch "Broad stop support ear" plane through (-36, 0, 0) normal (1, 0, 0) x axis (0, 0, -1)
  line L1 (-60, -20) -> (-60, -44)
  line L2 (-90, -20) -> (-60, -20)
  line L3 (-90, -44) -> (-90, -20)
  line L4 (-60, -44) -> (-90, -44)
extrude "Extrude10" add sketch "Broad stop support ear" along normal blind 12
work_plane "WorkPlane11" AlongDistance -24 ExtraOffset 0
sketch "Integrated steel-core end stop" plane through (-24, 0, 0) normal (1, 0, 0) x axis (0, 0, -1)
  circle C1 centre (-79.6754, -33.9652) radius 6
extrude "Extrude11" add sketch "Integrated steel-core end stop" along normal blind 15
work_plane "WorkPlane12" AlongDistance -36.1 ExtraOffset 0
